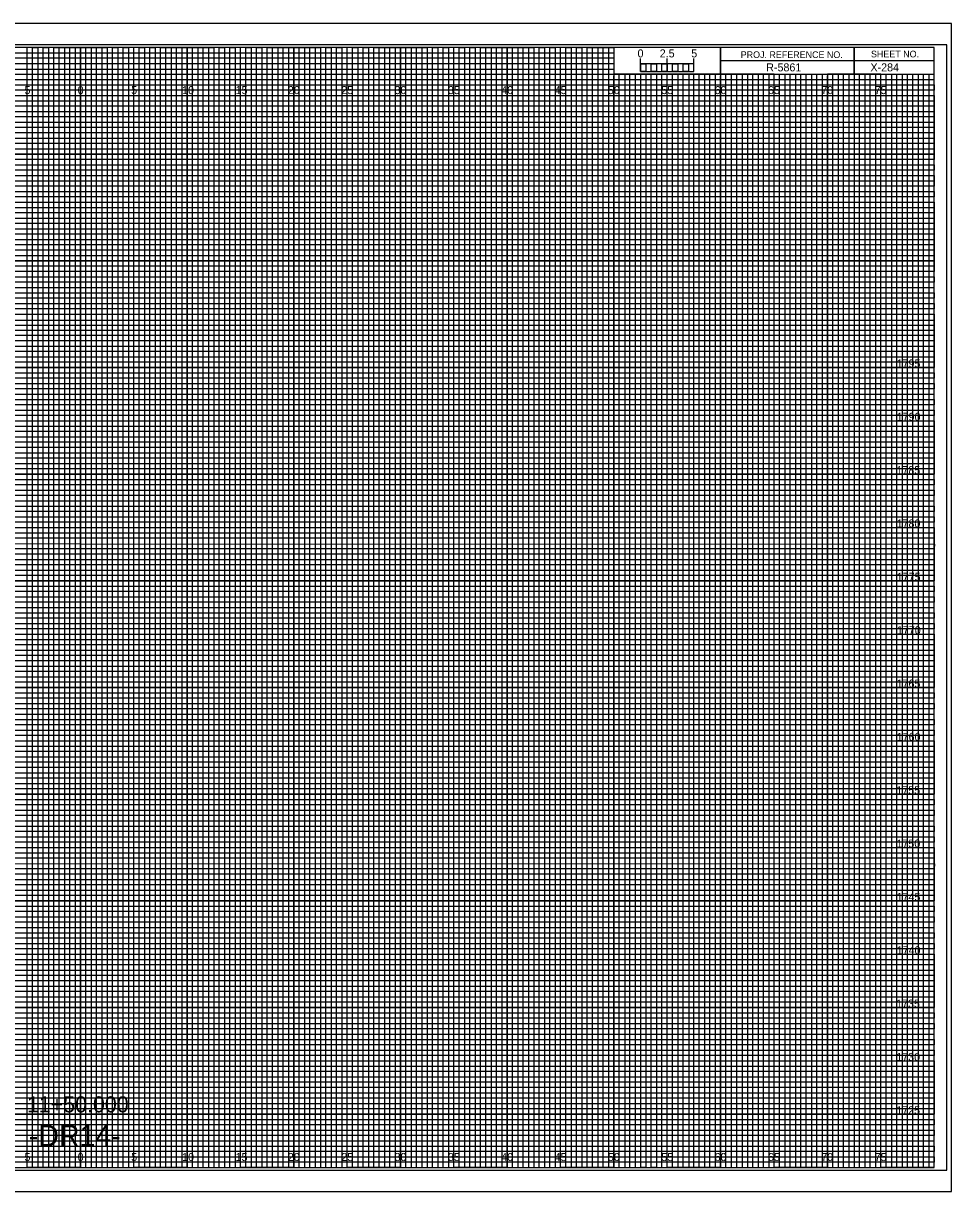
# Model space of a CAD drawing. Extents: x -7 to 162, y -2 to 437.
# Drawn here: x 74.6 to 161.7, y 217.7 to 327.2 of the extents above; entities that cross this region are included whole.
import ezdxf

# ---------------------------------------------------------------- set-up
doc = ezdxf.new("R2010")
doc.units = 0
for name, color, linetype in [('Prop Horizontal Alignment', 7, 'Continuous'), ('Prop XS Alignment Label', 7, 'Continuous'), ('Prop XS Bar Scale Labels', 7, 'Continuous'), ('Prop XS Project Number', 7, 'Continuous'), ('Prop XS Sheet Number', 7, 'Continuous'), ('Raster_Level_0', 7, 'Continuous'), ('Scratch_Level_3', 7, 'Continuous'), ('Sheet Cross Section CELL', 7, 'Continuous'), ('Sheet Cross Section Grid Major CELL', 7, 'Continuous'), ('Sheet Cross Section Grid Middle CELL', 7, 'Continuous'), ('Sheet Cross Section Grid Minor 1 CELL', 7, 'Continuous'), ('Sheet Cross Section Grid Minor 2 CELL', 7, 'Continuous'), ('Sheet Cross Section Scale CELL', 7, 'Continuous'), ('Sheet Cutting Line CELL', 7, 'Continuous'), ('Sheet DOT Grid CELL', 7, 'Continuous'), ('Sheet Plot Border Inside CELL', 7, 'Continuous'), ('Sheet Plot Border Outside CELL', 7, 'Continuous')]:
    doc.layers.add(name, color=color, linetype=linetype)

msp = doc.modelspace()

# ---------------------------------------------------------------- linework, layer by layer
at = {"layer": 'Sheet Cross Section CELL'}
for p, q in [((152.5, 325), (152.5, 322.5)), ((152.5, 322.5), (152.5, 325)), ((160, 323.75), (140, 323.75)), ((140, 323.75), (140, 322.5)), ((140, 322.5), (160, 322.5))]:
    msp.add_line(p, q, dxfattribs=at)
for points in [[(160, 325), (0, 325), (0, 220), (160, 220)], [(140, 325), (130, 325), (130, 322.51), (140, 322.51)], [(160, 325), (140, 325), (140, 322.5), (160, 322.5)]]:
    msp.add_lwpolyline(points, close=True, dxfattribs=at)
at = {"layer": 'Sheet Cross Section Grid Major CELL'}
for p, q in [((75, 325), (70, 325)), ((75, 220), (75, 325)), ((85, 325), (80, 325)), ((80, 325), (80, 220)), ((85, 220), (85, 325)), ((95, 325), (90, 325)), ((90, 325), (90, 220)), ((95, 220), (95, 325)), ((105, 325), (100, 325)), ((100, 325), (100, 220)), ((105, 220), (105, 325)), ((115, 325), (110, 325)), ((110, 325), (110, 220)), ((115, 220), (115, 325)), ((125, 325), (120, 325)), ((120, 325), (120, 220)), ((125, 220), (125, 325)), ((130, 325), (130, 220)), ((135, 220), (135, 322.5)), ((145, 322.5), (140, 322.5)), ((140, 322.5), (140, 220)), ((145, 220), (145, 322.5)), ((155, 322.5), (150, 322.5)), ((150, 322.5), (150, 220)), ((155, 220), (155, 322.5)), ((80, 220), (75, 220)), ((90, 220), (85, 220)), ((100, 220), (95, 220)), ((110, 220), (105, 220)), ((120, 220), (115, 220)), ((130, 220), (125, 220)), ((140, 220), (135, 220)), ((150, 220), (145, 220)), ((160, 220), (155, 220)), ((160, 220), (160, 220))]:
    msp.add_line(p, q, dxfattribs=at)
for points in [[(0, 320), (160, 320), (160, 315), (0, 315)], [(0, 310), (160, 310), (160, 305), (0, 305)], [(0, 300), (160, 300), (160, 295), (0, 295)], [(0, 290), (160, 290), (160, 285), (0, 285)], [(0, 280), (160, 280), (160, 275), (0, 275)], [(0, 270), (160, 270), (160, 265), (0, 265)], [(0, 260), (160, 260), (160, 255), (0, 255)], [(0, 250), (160, 250), (160, 245), (0, 245)], [(0, 240), (160, 240), (160, 235), (0, 235)], [(0, 230), (160, 230), (160, 225), (0, 225)]]:
    msp.add_lwpolyline(points, dxfattribs=at)
at = {"layer": 'Sheet Cross Section Grid Middle CELL'}
for points in [[(72.5, 220), (77.5, 220), (77.5, 325), (82.5, 325), (82.5, 220), (87.5, 220), (87.5, 325), (92.5, 325), (92.5, 220), (97.5, 220), (97.5, 325), (102.5, 325), (102.5, 220), (107.5, 220), (107.5, 325), (112.5, 325), (112.5, 220), (117.5, 220), (117.5, 325), (122.5, 325), (122.5, 220), (127.5, 220), (127.5, 325), (129.97, 325), (130, 325), (130, 322.5), (132.5, 322.5), (132.5, 220), (137.5, 220), (137.5, 322.5), (142.5, 322.5), (142.5, 220), (147.5, 220), (147.5, 322.5), (152.5, 322.5), (152.5, 220), (157.5, 220), (157.5, 322.5)], [(0, 322.5), (137.5, 322.5)], [(0, 312.5), (160, 312.5), (160, 317.5), (0, 317.5)], [(0, 302.5), (160, 302.5), (160, 307.5), (0, 307.5)], [(0, 292.5), (160, 292.5), (160, 297.5), (0, 297.5)], [(0, 282.5), (160, 282.5), (160, 287.5), (0, 287.5)], [(0, 272.5), (160, 272.5), (160, 277.5), (0, 277.5)], [(0, 262.5), (160, 262.5), (160, 267.5), (0, 267.5)], [(0, 252.5), (160, 252.5), (160, 257.5), (0, 257.5)], [(0, 242.5), (160, 242.5), (160, 247.5), (0, 247.5)], [(0, 232.5), (160, 232.5), (160, 237.5), (0, 237.5)], [(0, 222.5), (160, 222.5), (160, 227.5), (0, 227.5)]]:
    msp.add_lwpolyline(points, dxfattribs=at)
at = {"layer": 'Sheet Cross Section Grid Minor 1 CELL'}
for p, q in [((0, 324.5), (130, 324.5)), ((130, 324.5), (130, 323.99)), ((130, 323.99), (0, 323.99)), ((0, 323.5), (130, 323.5)), ((130, 323.5), (130, 322.94)), ((130, 322.94), (0, 322.94)), ((0, 322), (160, 322))]:
    msp.add_line(p, q, dxfattribs=at)
for points in [[(0, 321.5), (135, 321.5), (160, 321.5), (160, 321), (0, 321)], [(0, 320.5), (160, 320.5), (160, 319.5), (0, 319.5)], [(0, 319), (160, 319), (160, 318.5), (0, 318.49)], [(0, 318), (160, 318), (160, 317), (0, 317)], [(0, 316.5), (160, 316.5), (160, 316), (0, 316)], [(0, 315.5), (160, 315.5), (160, 314.5), (0, 314.5)], [(0, 314), (160, 314), (160, 313.5), (0, 313.5)], [(0, 313), (160, 313), (160, 312), (0, 312)], [(0, 311.5), (160, 311.5), (160, 311), (0, 311)], [(0, 310.5), (160, 310.5), (160, 309.5), (0, 309.5)], [(0, 309), (160, 309), (160, 308.5), (0, 308.5)], [(0, 308), (160, 308), (160, 306.98), (160, 306.5), (160, 306), (0, 306)], [(0, 307), (160, 307), (160, 306.5), (0, 306.5)], [(0, 305.5), (160, 305.5), (160, 304.5), (0, 304.51)], [(0, 304.51), (160, 304.5), (160, 304), (0, 304)], [(0, 303.5), (160, 303.5), (160, 303), (0, 303)], [(0, 302), (160, 302), (160, 301.5), (0, 301.5)], [(0, 301), (160, 301), (160, 300.5), (0, 300.5)], [(-0.04, 299.44), (160, 299.44), (160, 298.94), (-0.04, 298.94)], [(0, 298.5), (160, 298.5), (160, 298), (0, 298)], [(0, 297), (160, 297), (160, 296.5), (0, 296.5)], [(0, 296), (160, 296), (160, 295.5), (0, 295.5)], [(0, 294.5), (160, 294.5), (160, 294), (0, 294)], [(0, 293.5), (160, 293.5), (160, 293), (0, 293)], [(0, 292), (160, 292), (160, 291.5), (0, 291.5)], [(0, 291), (160, 291), (160, 290.5), (0, 290.5)], [(0, 289.5), (160, 289.5), (160, 288.99), (0, 289)], [(0, 288.5), (160, 288.5), (160, 288), (0, 288)], [(0, 287), (160, 287), (160, 286.5), (0, 286.5)], [(0, 286), (160, 286), (160, 285.5), (0, 285.5)], [(0, 284.5), (160, 284.5), (160, 284), (0, 284)], [(0, 283.5), (160, 283.5), (160, 283), (0, 283)], [(0, 282), (160, 282), (160, 281.5), (0, 281.5)], [(0, 281), (160, 281), (160, 280.5), (0, 280.5)], [(0, 279.5), (160, 279.5), (160, 279), (0, 279)], [(0, 278.5), (160.03, 278.45), (160, 278), (0, 278)], [(0, 277), (160, 277), (160, 276.5), (0, 276.5)], [(0, 276), (160, 276), (160, 275.5), (0, 275.5)], [(0, 274.5), (160, 274.5), (160, 274), (0, 274)], [(0, 273.5), (160, 273.5), (160, 273), (0, 273)], [(0, 272), (160, 272), (160, 271.5), (0, 271.5)], [(0, 271), (160, 271), (160, 270.5), (0, 270.5)], [(0, 269.5), (160, 269.5), (160, 269), (0, 269)], [(0, 268.5), (160, 268.5), (160, 268), (0, 268)], [(0, 267), (160, 267), (160, 266.5), (0, 266.5)], [(0, 266), (160, 266), (160, 265.5), (0, 265.5)], [(0, 264.5), (160, 264.5), (160, 264), (0, 264)], [(0, 263.5), (160, 263.5), (160, 263), (0, 263)], [(0, 262), (160, 262), (160, 261.5), (0, 261.5)], [(0, 261), (160, 261), (160, 260.5), (0, 260.5)], [(0, 259.5), (160, 259.5), (160, 258.99), (0, 259)], [(0, 258.5), (160, 258.5), (160, 258), (0, 258)], [(0, 257), (160, 257), (160, 256.5), (0, 256.5)], [(0, 256), (160, 256), (160, 255.5), (0, 255.5)], [(0, 254.5), (160, 254.5), (160, 254), (0, 254)], [(0, 253.5), (160, 253.5), (160, 253), (0, 253)], [(0, 252), (160, 252), (160, 251.5), (0, 251.5)], [(0, 251), (160, 251), (160, 250.5), (0, 250.5)], [(0, 249.5), (160, 249.5), (160, 249), (0, 249)], [(0, 248.5), (160.03, 248.46), (160, 248), (0, 248)], [(0, 247), (160, 247), (160, 246.5), (0, 246.5)], [(0, 246), (160, 246), (160, 245.5), (0, 245.5)], [(0, 244.5), (160, 244.5), (160, 244), (0, 244)], [(0, 243.5), (160, 243.5), (160, 243), (0, 243)], [(0, 242), (160, 242), (160, 241.5), (0, 241.5)], [(0, 241), (160, 241), (160, 240.5), (0, 240.5)], [(0, 239.5), (160, 239.5), (160, 239), (0, 239)], [(0, 238.5), (160, 238.5), (160, 238), (0, 238)], [(0, 237), (160, 237), (160, 236.5), (0, 236.5)], [(0, 236), (160, 236), (160, 235.5), (0, 235.5)], [(0, 234.5), (160, 234.5), (160, 234), (0, 234)], [(0, 233.5), (160, 233.5), (160, 233), (0, 233)], [(0, 232), (160, 232), (160, 231.5), (0, 231.5)], [(0, 231), (160, 231), (160, 230.5), (0, 230.5)], [(0, 229.5), (160, 229.5), (160, 229), (0, 229)], [(0, 228.5), (160, 228.5), (160, 228), (0, 228)], [(0, 227), (160, 227), (160, 226.5), (0, 226.5)], [(0, 226), (160, 226), (160, 225.5), (0, 225.5)], [(0, 224.5), (160, 224.5), (160, 224), (0, 224)], [(0, 223.5), (160, 223.5), (160, 223), (0, 223)], [(0, 222), (160, 222), (160, 221.5), (0, 221.5)], [(0, 221), (160, 221), (160, 220.5), (0, 220.5)]]:
    msp.add_lwpolyline(points, dxfattribs=at)
at = {"layer": 'Sheet Cross Section Grid Minor 2 CELL'}
for p, q in [((133.5, 322.5), (133, 322.5)), ((133, 322.5), (133, 220)), ((133.5, 220), (133.5, 322.5)), ((134.5, 322.5), (134, 322.5)), ((134, 322.5), (134, 220)), ((134.5, 220), (134.5, 322.5)), ((133, 220), (132.5, 220)), ((134, 220), (133.5, 220))]:
    msp.add_line(p, q, dxfattribs=at)
for points in [[(75, 220), (75.5, 220), (75.5, 325), (76, 325), (76, 220)], [(76, 220), (76.5, 220), (76.5, 325), (77, 325), (77, 220)], [(77.5, 220), (78, 220), (78, 325), (78.5, 325), (78.5, 220)], [(78.5, 220), (79, 220), (79, 325), (79.5, 325), (79.5, 220)], [(80, 220), (80.5, 220), (80.5, 325), (81, 325), (81, 220)], [(81, 220), (81.5, 220), (81.5, 325), (82, 325), (82, 220)], [(82.5, 220), (83, 220), (83, 325), (83.5, 325), (83.5, 220)], [(83.5, 220), (84, 220), (84, 325), (84.5, 325), (84.5, 220)], [(85, 220), (85.5, 220), (85.5, 325), (86, 325), (86, 220)], [(86, 220), (86.5, 220), (86.5, 325), (87, 325), (87, 220)], [(87.5, 220), (88, 220), (88, 325), (88.5, 325), (88.5, 220)], [(88.5, 220), (89, 220), (89, 325), (89.5, 325), (89.5, 220)], [(90, 220), (90.5, 220), (90.5, 325), (91, 325), (91, 220)], [(91, 220), (91.5, 220), (91.5, 325), (92, 325), (92, 220)], [(92.5, 220), (93, 220), (93, 325), (93.5, 325), (93.5, 220)], [(93.5, 220), (94, 220), (94, 325), (94.5, 325), (94.5, 220)], [(95, 220), (95.5, 220), (95.5, 325), (96, 325), (96, 220)], [(96, 220), (96.5, 220), (96.5, 325), (97, 325), (97, 220)], [(97.5, 220), (98, 220), (98, 325), (98.5, 325), (98.5, 220)], [(98.5, 220), (99, 220), (99, 325), (99.5, 325), (99.5, 220)], [(100, 220), (100.5, 220), (100.5, 325), (101, 325), (101, 220)], [(101, 220), (101.5, 220), (101.5, 325), (102, 325), (102, 220)], [(102.5, 220), (103, 220), (103, 325), (103.5, 325), (103.5, 220)], [(103.5, 220), (104, 220), (104, 325), (104.5, 325), (104.5, 220)], [(105, 220), (105.5, 220), (105.5, 325), (106, 325), (106, 220)], [(106, 220), (106.5, 220), (106.5, 325), (107, 325), (107, 220)], [(107.5, 220), (108, 220), (108, 325), (108.5, 325), (108.5, 220)], [(108.5, 220), (109, 220), (109, 325), (109.5, 325), (109.5, 220)], [(110, 220), (110.5, 220), (110.5, 325), (111, 325), (111, 220)], [(111, 220), (111.5, 220), (111.5, 325), (112, 325), (112, 220)], [(112.5, 220), (113, 220), (113, 325), (113.5, 325), (113.5, 220)], [(113.5, 220), (114, 220), (114, 325), (114.5, 325), (114.5, 220)], [(115, 220), (115.5, 220), (115.5, 325), (116, 325), (116, 220)], [(116, 220), (116.5, 220), (116.5, 325), (117, 325), (117, 220)], [(117.5, 220), (118, 220), (118, 325), (118.5, 325), (118.5, 220)], [(118.5, 220), (119, 220), (119, 325), (119.5, 325), (119.5, 220)], [(120, 220), (120.5, 220), (120.5, 325), (121, 325), (121, 220)], [(121, 220), (121.5, 220), (121.5, 325), (122, 325), (122, 220)], [(122.5, 220), (123, 220), (123, 325), (123.5, 325), (123.5, 220)], [(123.5, 220), (124, 220), (124, 325), (124.5, 325), (124.5, 220)], [(125, 220), (125.5, 220), (125.5, 325), (126, 325), (126, 220)], [(126, 220), (126.5, 220), (126.5, 325), (127, 325), (127, 220)], [(127.5, 220), (128, 220), (128, 325), (128.5, 325), (128.5, 220)], [(128.5, 220), (129, 220), (129, 325), (129.5, 325), (129.5, 220)], [(130, 220), (130.5, 220), (130.5, 322.5), (131.01, 322.5), (131.01, 220)], [(131, 220), (131.5, 220), (131.5, 322.5), (132, 322.5), (132, 220)], [(135, 220), (135.49, 220), (135.49, 322.5), (136, 322.5), (136, 220)], [(136, 220), (136.5, 220), (136.5, 322.5), (137.03, 322.5), (137.03, 220)], [(137.5, 220), (138, 220), (138, 322.5), (138.5, 322.5), (138.5, 220)], [(138.5, 220), (139, 220), (139, 322.5), (139.5, 322.5), (139.5, 220)], [(140, 220), (140.5, 220), (140.5, 322.5), (141, 322.5), (141, 220)], [(141, 220), (141.5, 220), (141.5, 322.5), (142, 322.5), (142, 220)], [(142.5, 220), (143, 220), (143, 322.5), (143.5, 322.5), (143.5, 220)], [(143.5, 220), (144, 220), (144, 322.5), (144.5, 322.5), (144.5, 220)], [(145, 220), (145.5, 220), (145.5, 322.5), (146, 322.5), (146, 220)], [(146, 220), (146.5, 220), (146.5, 322.5), (147, 322.5), (147, 220)], [(147.5, 220), (148, 220), (148, 322.5), (148.5, 322.5), (148.5, 220)], [(148.5, 220), (149, 220), (149, 322.5), (149.5, 322.5), (149.5, 220)], [(150, 220), (150.5, 220), (150.5, 322.5), (151, 322.5), (151, 220)], [(151, 220), (151.5, 220), (151.5, 322.5), (152, 322.5), (152, 220)], [(152.5, 220), (153, 220), (153, 322.5), (153.5, 322.5), (153.5, 220)], [(153.5, 220), (154, 220), (154, 322.5), (154.5, 322.5), (154.5, 220)], [(155, 220), (155.5, 220), (155.5, 322.5), (156, 322.5), (156, 220)], [(156, 220), (156.5, 220), (156.5, 322.5), (157, 322.5), (157, 220)], [(157.5, 220), (158, 220), (158, 322.5), (158.5, 322.5), (158.5, 220)], [(158.5, 220), (159, 220), (159, 322.5), (159.5, 322.5), (159.5, 220)]]:
    msp.add_lwpolyline(points, dxfattribs=at)
at = {"layer": 'Sheet Cross Section Scale CELL'}
for p, q in [((132.5, 322.75), (132.5, 323.95)), ((132.5, 323.45), (132.5, 323.95)), ((135, 322.75), (135, 323.95)), ((137.5, 322.75), (137.5, 323.95)), ((137.5, 323.45), (137.5, 323.95))]:
    msp.add_line(p, q, dxfattribs=at)
for points in [[(137.5, 323.45), (132.5, 323.45), (132.5, 322.75), (137.5, 322.75)], [(132.5, 323.45), (133, 323.45), (133, 322.75), (132.5, 322.75)], [(133.5, 323.45), (134, 323.45), (134, 322.75), (133.5, 322.75)], [(134.5, 323.45), (135, 323.45), (135, 322.75), (134.5, 322.75)], [(135.5, 323.45), (136, 323.45), (136, 322.75), (135.5, 322.75)], [(136.5, 323.45), (137, 323.45), (137, 322.75), (136.5, 322.75)]]:
    msp.add_lwpolyline(points, close=True, dxfattribs=at)
at = {"layer": 'Sheet Cutting Line CELL'}
for p, q in [((161.65, 327.25), (-6.7, 327.25)), ((-6.7, 217.75), (161.65, 217.75))]:
    msp.add_line(p, q, dxfattribs=at)
at = {"layer": 'Sheet DOT Grid CELL'}
for p, q in [((75, 220), (75, 325)), ((80, 220), (80, 325)), ((85, 220), (85, 325)), ((90, 220), (90, 325)), ((95, 220), (95, 325)), ((100, 220), (100, 325)), ((105, 220), (105, 325)), ((110, 220), (110, 325)), ((115, 220), (115, 325)), ((120, 220), (120, 325)), ((125, 220), (125, 325)), ((130, 220), (130, 322.34)), ((135, 220), (135, 322.34)), ((140, 220), (140, 322.34)), ((145, 220), (145, 322.34)), ((150, 220), (150, 322.34)), ((155, 220), (155, 322.34)), ((0, 320), (160, 320)), ((0, 315), (160, 315)), ((0, 310), (160, 310)), ((0, 305), (160, 305)), ((0, 300), (160, 300)), ((0, 295), (160, 295)), ((0, 290), (160, 290)), ((0, 285), (160, 285)), ((0, 280), (160, 280)), ((0, 275), (160, 275)), ((0, 270), (160, 270)), ((0, 265), (160, 265)), ((0, 260), (160, 260)), ((0, 255), (160, 255)), ((0, 250), (160, 250)), ((0, 245), (160, 245)), ((0, 240), (160, 240)), ((0, 235), (160, 235)), ((0, 230), (160, 230)), ((0, 225), (160, 225))]:
    msp.add_line(p, q, dxfattribs=at)
at = {"layer": 'Sheet Plot Border Inside CELL'}
msp.add_lwpolyline([(-5.4, 219.75), (161.2, 219.75), (161.2, 325.25), (-5.4, 325.25)], close=True, dxfattribs=at)
at = {"layer": 'Sheet Plot Border Outside CELL'}
msp.add_lwpolyline([(-6.7, 217.75), (161.65, 217.75), (161.65, 327.25), (-6.7, 327.25)], close=True, dxfattribs=at)

# ---------------------------------------------------------------- texts
at = {"layer": 'Prop Horizontal Alignment'}
msp.add_text('11+50.000', height=1.5, dxfattribs=at).set_placement((74.97, 225.18))
at = {"layer": 'Prop XS Alignment Label'}
msp.add_text('-DR14-', height=2, dxfattribs=at).set_placement((75.15, 222))
at = {"layer": 'Prop XS Bar Scale Labels'}
for s, p in [('2.5', (134.29, 324.06)), ('5', (137.24, 324.06))]:
    msp.add_text(s, height=0.75, dxfattribs=at).set_placement(p)
at = {"layer": 'Prop XS Project Number'}
msp.add_text('R-5861', height=0.75, dxfattribs=at).set_placement((144.27, 322.75))
at = {"layer": 'Prop XS Sheet Number'}
msp.add_text('X-284', height=0.75, dxfattribs=at).set_placement((154.04, 322.75))
at = {"layer": 'Raster_Level_0'}
for s, p in [('5', (74.74, 320.62)), ('0', (79.73, 320.62)), ('0', (79.73, 320.62)), ('5', (84.74, 320.62)), ('10', (89.52, 320.62)), ('15', (94.53, 320.62)), ('20', (99.43, 320.62)), ('25', (104.44, 320.62)), ('30', (109.43, 320.62)), ('35', (114.44, 320.62)), ('40', (119.43, 320.62)), ('45', (124.44, 320.62)), ('50', (129.43, 320.62)), ('55', (134.44, 320.62)), ('60', (139.43, 320.62)), ('65', (144.44, 320.62)), ('70', (149.43, 320.62)), ('75', (154.44, 320.62)), ('5', (74.74, 220.62)), ('0', (79.73, 220.62)), ('0', (79.73, 220.62)), ('5', (84.74, 220.62)), ('10', (89.52, 220.62)), ('15', (94.53, 220.62)), ('20', (99.43, 220.62)), ('25', (104.44, 220.62)), ('30', (109.43, 220.62)), ('35', (114.44, 220.62)), ('40', (119.43, 220.62)), ('45', (124.44, 220.62)), ('50', (129.43, 220.62)), ('55', (134.44, 220.62)), ('60', (139.43, 220.62)), ('65', (144.44, 220.62)), ('70', (149.43, 220.62)), ('75', (154.44, 220.62))]:
    msp.add_text(s, height=0.75, dxfattribs=at).set_placement(p)
at = {"layer": 'Scratch_Level_3'}
for s, p in [('1795', (156.49, 295)), ('1790', (156.5, 290)), ('1785', (156.48, 285)), ('1780', (156.49, 280)), ('1775', (156.51, 275)), ('1770', (156.52, 270)), ('1765', (156.49, 265)), ('1760', (156.5, 260)), ('1755', (156.47, 255)), ('1750', (156.48, 250)), ('1745', (156.49, 245)), ('1740', (156.5, 240)), ('1735', (156.45, 235)), ('1730', (156.46, 230)), ('1725', (156.46, 225))]:
    msp.add_text(s, height=0.75, dxfattribs=at).set_placement(p)
at = {"layer": 'Sheet Cross Section CELL'}
for s, p in [('PROJ. REFERENCE NO.', (141.88, 324)), ('SHEET NO.', (154.09, 324.06))]:
    msp.add_text(s, height=0.625, dxfattribs=at).set_placement(p)
at = {"layer": 'Sheet Cross Section Scale CELL'}
msp.add_text('0', height=0.75, dxfattribs=at).set_placement((132.21, 324.06))

doc.saveas('drawing.dxf')
